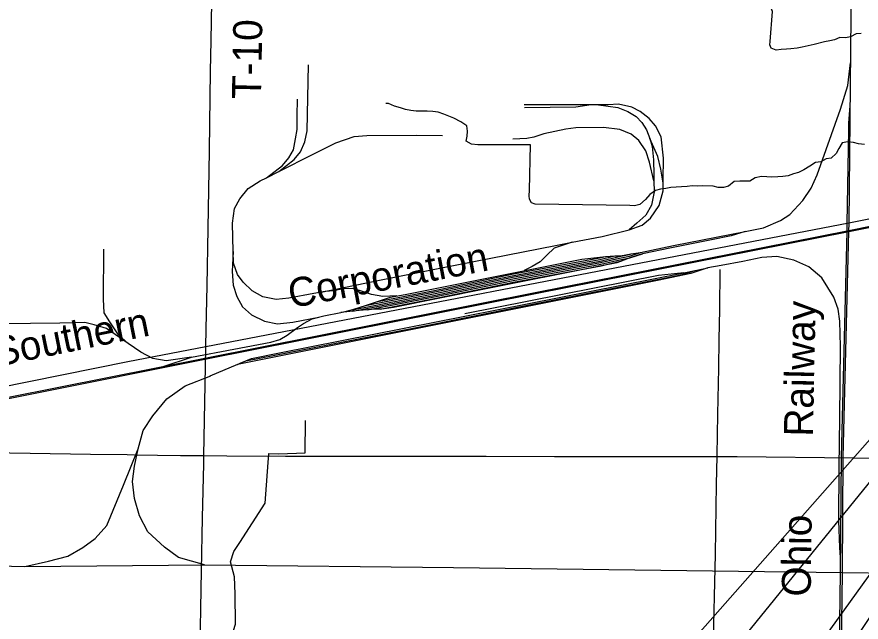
# Model space of a CAD drawing. Extents: x -21.7 to 34, y 0 to 22.
# Drawn here: x 24.265 to 25.914, y 16.163 to 17.347 of the extents above; entities that cross this region are included whole.
import ezdxf

# ---------------------------------------------------------------- set-up
doc = ezdxf.new("R2010")
doc.units = 0
for name, color, linetype in [('GM_X_County_Road', 7, 'Continuous'), ('GM_X_Minor_River', 7, 'Continuous'), ('GM_X_Rail_Line', 7, 'Continuous'), ('GM_X_Rail_Line_Text', 7, 'Continuous'), ('GM_X_Township_Road', 7, 'Continuous'), ('GM_X_Township_Road_Text', 7, 'Continuous'), ('SH_Text', 7, 'Continuous')]:
    doc.layers.add(name, color=color, linetype=linetype)

msp = doc.modelspace()

# ---------------------------------------------------------------- linework, layer by layer
at = {"layer": 'GM_X_County_Road'}
for points in [[(23.6256, 16.4644), (23.6379, 16.4668), (23.6898, 16.4767), (23.7751, 16.4941), (23.7934, 16.4974), (23.8057, 16.499), (23.818, 16.5001), (23.8304, 16.5007), (23.8521, 16.5009), (23.9236, 16.4998), (23.9951, 16.4988), (24.0915, 16.4969), (24.2904, 16.4939), (24.4085, 16.4918), (24.4798, 16.491), (24.4945, 16.4906), (24.5845, 16.4894), (24.6301, 16.4891)], [(24.6301, 16.4891), (24.6746, 16.4888), (24.7897, 16.488), (24.8643, 16.4882), (24.8953, 16.4881), (24.9451, 16.488), (25.0104, 16.488), (25.0725, 16.4878), (25.1223, 16.4878), (25.1813, 16.4879), (25.3149, 16.4876), (25.346, 16.4875), (25.4734, 16.4872), (25.5014, 16.4871), (25.6319, 16.4875), (25.6331, 16.4875)], [(25.6331, 16.4875), (25.6723, 16.4872), (25.8993, 16.4845), (25.966, 16.4842)]]:
    msp.add_lwpolyline(points, dxfattribs=at)
at = {"layer": 'GM_X_Minor_River'}
for points in [[(25.7364, 17.2987), (25.7411, 17.3574), (25.7379, 17.3662), (25.7315, 17.369), (25.712, 17.3748), (25.6478, 17.391), (25.6434, 17.3975), (25.6414, 17.4075), (25.636, 17.4194), (25.6031, 17.4402), (25.5644, 17.4395)], [(25.9147, 17.3144), (25.9048, 17.3139), (25.8933, 17.3081), (25.8837, 17.306), (25.8727, 17.3063), (25.8624, 17.3019), (25.8529, 17.3003), (25.8429, 17.2978), (25.8223, 17.293), (25.8109, 17.2906), (25.7991, 17.2874), (25.7892, 17.2854), (25.777, 17.2843), (25.7683, 17.2835), (25.758, 17.283), (25.7485, 17.2821), (25.7383, 17.2854), (25.7362, 17.2924), (25.7364, 17.2987)], [(25.1652, 17.097), (25.1527, 17.098), (25.1426, 17.1036), (25.1444, 17.1134), (25.1453, 17.1236), (25.1437, 17.1339), (25.1321, 17.1418), (25.1182, 17.1489), (25.0987, 17.1569), (25.0878, 17.1606), (25.0772, 17.1616), (25.0662, 17.1626), (25.0548, 17.1625), (25.045, 17.1627), (25.0344, 17.1637), (25.0238, 17.1658), (25.014, 17.1691), (25.0023, 17.1724), (24.9907, 17.1776), (24.9857, 17.1777)], [(25.4625, 16.978), (25.2771, 16.9806), (25.2699, 16.9835), (25.2663, 16.9907), (25.2657, 16.9972), (25.2663, 17.0078), (25.2684, 17.0966), (25.1652, 17.097)], [(25.921, 17.0972), (25.9093, 17.0986), (25.8995, 17.1015), (25.8881, 17.1029), (25.877, 17.1004), (25.8707, 17.0896), (25.8656, 17.0795), (25.8559, 17.0709), (25.8463, 17.0693), (25.8356, 17.0638), (25.8253, 17.0621), (25.8138, 17.0548), (25.8022, 17.0478), (25.7919, 17.0428), (25.7823, 17.0403), (25.7716, 17.036), (25.7613, 17.0351), (25.7514, 17.0342), (25.74, 17.0337), (25.7302, 17.0339), (25.7196, 17.0345), (25.7074, 17.0325), (25.697, 17.0259), (25.6867, 17.0254), (25.6773, 17.0256), (25.6662, 17.0247), (25.6554, 17.0158), (25.6455, 17.013), (25.6352, 17.0136), (25.6254, 17.0161), (25.605, 17.0166), (25.5951, 17.0157), (25.5841, 17.0163), (25.5746, 17.015), (25.5636, 17.0148), (25.5423, 17.013), (25.5324, 17.0114), (25.5225, 17.0101), (25.5126, 17.0073), (25.5017, 16.9995), (25.4932, 16.9899), (25.4822, 16.9799), (25.4712, 16.9777), (25.4625, 16.978)], [(24.7767, 16.4927), (24.8276, 16.4946), (24.8286, 16.5576)], [(24.1157, 15.4505), (24.1225, 15.4647), (24.1423, 15.4696), (24.1622, 15.4741), (24.1812, 15.4756), (24.1982, 15.4752), (24.4418, 15.4747), (24.4643, 15.495), (24.5971, 15.4958), (24.6104, 16.0334), (24.6316, 16.047), (24.6541, 16.0677), (24.6743, 16.1033), (24.6915, 16.1595), (24.6914, 16.2191), (24.6895, 16.2518), (24.6818, 16.2815), (24.6888, 16.3019), (24.7005, 16.3195), (24.7498, 16.3958), (24.757, 16.4932), (24.7767, 16.4927)]]:
    msp.add_lwpolyline(points, dxfattribs=at)
at = {"layer": 'GM_X_Rail_Line'}
for p, q in [((25.401, 17.175), (25.3871, 17.175)), ((24.7523, 17.0321), (24.7765, 17.0445)), ((25.4147, 16.8783), (25.433, 16.8794)), ((25.4647, 16.8833), (25.4834, 16.8862)), ((25.568, 16.8466), (25.5897, 16.8509)), ((25.5897, 16.8509), (25.6147, 16.8559)), ((24.9212, 16.7713), (24.8978, 16.7692)), ((24.6957, 16.6673), (24.6413, 16.6441)), ((24.2799, 16.272), (24.6309, 16.2756))]:
    msp.add_line(p, q, dxfattribs=at)
for points in [[(25.8368, 14.1), (25.8424, 14.4841), (25.8672, 15.4825), (25.8776, 16.2603), (25.8795, 16.4862), (25.8906, 16.927), (25.8907, 16.9438), (25.8961, 17.4845), (25.9239, 18.7551), (25.935, 19.5978), (25.9554, 20.5461), (25.9616, 20.9)], [(23.5167, 16.459), (23.6295, 16.4808), (23.9621, 16.5465), (24.6321, 16.6797), (25.2774, 16.8081), (25.8901, 16.9293), (26.3845, 17.0293), (27.0776, 17.1675), (27.7467, 17.2984), (28.3715, 17.4275), (28.9889, 17.5495), (29.6221, 17.6814), (30.2791, 17.8098), (30.3167, 17.8172)], [(25.8905, 16.9443), (26.7077, 17.1083), (26.7688, 17.1586), (26.8119, 17.2101), (26.8634, 17.276), (26.8946, 17.3324), (26.9509, 17.3923), (27.006, 17.4474), (27.0347, 17.4689), (27.0802, 17.4809), (27.5534, 17.4838), (27.9584, 17.4827), (28.1647, 17.4796), (28.575, 17.4796), (29.0617, 17.5773), (30.0904, 17.7802), (30.3167, 17.8248)], [(23.5167, 16.4567), (23.6289, 16.4784), (23.9619, 16.5433), (24.6317, 16.6775), (25.2779, 16.8058), (25.8906, 16.927), (26.3849, 17.0271), (27.078, 17.1653), (27.7471, 17.2961), (28.3719, 17.4252), (28.9894, 17.5472), (29.6225, 17.6791), (30.2796, 17.8076), (30.3167, 17.8149)], [(25.6876, 16.927), (25.7233, 16.9345), (25.757, 16.9485), (25.7751, 16.9608), (25.8006, 16.988), (25.817, 17.0118), (25.8285, 17.0381), (25.8737, 17.1664), (25.8884, 17.2129), (25.8938, 17.2569)], [(24.7765, 17.0445), (24.8063, 17.0679), (24.8191, 17.0831), (24.8273, 17.1024), (24.8318, 17.1242), (24.8343, 17.2532)], [(24.7523, 17.0321), (24.7833, 17.056), (24.7961, 17.0716), (24.8051, 17.0872), (24.8092, 17.1082), (24.8121, 17.1267), (24.8121, 17.1534), (24.8129, 17.1863)], [(25.3871, 17.175), (25.3513, 17.1747), (25.2556, 17.1747)], [(25.3871, 17.175), (25.3571, 17.1702), (25.2564, 17.169)], [(25.5275, 17.0218), (25.5277, 17.0276), (25.5281, 17.0708), (25.5235, 17.1123), (25.5124, 17.1336), (25.5001, 17.1484), (25.4824, 17.1616), (25.4664, 17.1706), (25.4401, 17.176), (25.42, 17.1752), (25.401, 17.175)], [(25.401, 17.175), (25.4389, 17.1698), (25.4586, 17.162), (25.475, 17.1521), (25.4857, 17.1406), (25.4952, 17.1262), (25.5013, 17.109)], [(25.8526, 14.8964), (25.8499, 14.9355), (25.8634, 15.4826), (25.8739, 16.2603), (25.8757, 16.4863), (25.8868, 16.9271), (25.887, 16.9438), (25.8904, 17.1251), (25.8905, 17.1392), (25.893, 17.1728)], [(25.5093, 17.0264), (25.5009, 17.0625), (25.4939, 17.0851), (25.48, 17.1053), (25.4648, 17.1176), (25.4426, 17.1267), (25.4109, 17.1304), (25.3571, 17.1299), (25.3374, 17.1275), (25.3156, 17.123), (25.2942, 17.1184), (25.2749, 17.1119), (25.2609, 17.1094), (25.2338, 17.1077)], [(24.7765, 17.0445), (24.8433, 17.0786), (24.8877, 17.1008), (24.9235, 17.1127), (24.9481, 17.1151), (25.0459, 17.1156), (25.0961, 17.1147)], [(25.5275, 17.0218), (25.5227, 17.0494), (25.517, 17.074), (25.5013, 17.109)], [(25.5013, 17.109), (25.5059, 17.0934), (25.5087, 17.0671), (25.5092, 17.0379), (25.5093, 17.0264)], [(24.6871, 16.8883), (24.6859, 16.9433), (24.69, 16.9725), (24.7003, 16.9914), (24.7163, 17.0112), (24.7402, 17.026), (24.7523, 17.0321)], [(25.5093, 17.0264), (25.5096, 17.0046), (25.5046, 16.9787), (25.4935, 16.9594), (25.4763, 16.9438), (25.4611, 16.9306)], [(25.4611, 16.9306), (25.4866, 16.9396), (25.503, 16.9536), (25.5194, 16.9783), (25.5272, 17.007), (25.5275, 17.0218)], [(23.5167, 16.4779), (24.4815, 16.6733), (25.8905, 16.9443)], [(25.3497, 16.9061), (25.408, 16.9174), (25.4611, 16.9306)], [(25.4834, 16.8862), (25.5475, 16.9), (25.6876, 16.927), (25.6603, 16.9185), (25.6221, 16.9109), (25.5406, 16.8948), (25.4903, 16.8843), (25.4871, 16.8833)], [(24.8561, 16.808), (24.9732, 16.8324), (25.094, 16.8562), (25.3172, 16.8998), (25.3497, 16.9061)], [(25.3497, 16.9061), (25.3143, 16.8944), (25.3, 16.8809), (25.2872, 16.8677), (25.2716, 16.8591), (25.2558, 16.8507)], [(24.4823, 16.708), (24.4634, 16.7252), (24.4461, 16.7507), (24.4354, 16.768), (24.4338, 16.7951), (24.4346, 16.8929)], [(24.6871, 16.8883), (24.6851, 16.8488), (24.6871, 16.8221), (24.6945, 16.7999), (24.7056, 16.7802), (24.7229, 16.7646), (24.7484, 16.7518), (24.7739, 16.7465), (24.8039, 16.7498), (24.8547, 16.76)], [(24.8561, 16.808), (24.8446, 16.8061), (24.7961, 16.797), (24.771, 16.7946), (24.7455, 16.7995), (24.7241, 16.811), (24.7069, 16.8283), (24.6958, 16.8435), (24.688, 16.8653), (24.6871, 16.8883)], [(24.9206, 16.7744), (25.0819, 16.8061), (25.2332, 16.8377), (25.4045, 16.8695), (25.4413, 16.8781), (25.4609, 16.882), (25.4647, 16.8833)], [(24.9212, 16.7713), (25.0826, 16.803), (25.2338, 16.8346), (25.4051, 16.8665), (25.4419, 16.8751), (25.4617, 16.879), (25.4834, 16.8862)], [(24.9461, 16.7826), (25.0813, 16.8091), (25.2326, 16.8407), (25.4038, 16.8726), (25.433, 16.8794)], [(24.95, 16.7738), (25.0832, 16.8), (25.2344, 16.8316), (25.4058, 16.8635), (25.4426, 16.872), (25.4625, 16.876), (25.4871, 16.8833)], [(24.969, 16.7902), (24.9944, 16.7991), (25.0263, 16.8047), (25.3686, 16.8734), (25.4097, 16.878), (25.4147, 16.8783)], [(24.969, 16.7902), (25.0807, 16.8122), (25.232, 16.8438), (25.4032, 16.8756), (25.4147, 16.8783)], [(25.433, 16.8794), (25.4439, 16.88), (25.4647, 16.8833)], [(25.4871, 16.8833), (25.4646, 16.8764), (25.4457, 16.8695)], [(25.8741, 16.29), (25.8725, 16.3092), (25.8708, 16.3614), (25.8713, 16.4666), (25.8725, 16.5623), (25.8741, 16.7025), (25.8729, 16.7518), (25.8696, 16.7752), (25.861, 16.7991), (25.8376, 16.8369), (25.8121, 16.8583), (25.7825, 16.871), (25.7496, 16.8784), (25.72, 16.8763), (25.683, 16.8685), (25.6411, 16.8611), (25.6147, 16.8559)], [(24.9744, 16.7754), (25.0838, 16.797), (25.235, 16.8285), (25.4064, 16.8604), (25.4433, 16.869), (25.4457, 16.8695)], [(25.4457, 16.8695), (25.4367, 16.8662), (25.4035, 16.8596), (25.1782, 16.8146), (25.0004, 16.7784), (24.9823, 16.7758), (24.9744, 16.7754)], [(25.6147, 16.8559), (25.5816, 16.8449), (25.5198, 16.8324), (24.6957, 16.6673)], [(24.7118, 16.6742), (25.0388, 16.7381), (25.2593, 16.7828), (25.5454, 16.8393), (25.5649, 16.8434), (25.5897, 16.8509)], [(24.7118, 16.6742), (24.7232, 16.679), (24.778, 16.6897), (25.568, 16.8466)], [(25.568, 16.8466), (25.5182, 16.8414), (25.1397, 16.7666)], [(25.0068, 16.8013), (24.9794, 16.8003), (24.9572, 16.804), (24.9362, 16.8114), (24.9202, 16.8155), (24.9009, 16.8151), (24.8848, 16.8114), (24.8667, 16.8098), (24.8561, 16.808)], [(24.5501, 16.6634), (24.6061, 16.6814), (24.6883, 16.6972), (24.7606, 16.7106), (24.7787, 16.7162), (24.7929, 16.7245), (24.8129, 16.7393), (24.8248, 16.7471), (24.8415, 16.7564), (24.8642, 16.7626), (24.8974, 16.7692), (24.9231, 16.7751), (24.9461, 16.7826)], [(24.9461, 16.7826), (24.9596, 16.7869), (24.969, 16.7902)], [(24.95, 16.7738), (24.9336, 16.7725), (24.9212, 16.7713)], [(24.9744, 16.7754), (24.9652, 16.7751), (24.95, 16.7738)], [(24.4823, 16.708), (24.4395, 16.7376), (24.4157, 16.745), (24.3976, 16.7491), (24.3483, 16.7482), (24.234, 16.7466)], [(24.6061, 16.6814), (24.5565, 16.6744), (24.5299, 16.6792), (24.5069, 16.6915), (24.4823, 16.708)], [(24.6957, 16.6673), (24.7007, 16.6695), (24.7118, 16.6742)], [(24.5015, 16.502), (24.5111, 16.538), (24.5302, 16.5667), (24.5578, 16.6003), (24.5937, 16.6255), (24.6433, 16.6448)], [(24.2799, 16.272), (24.3266, 16.2828), (24.3638, 16.2924), (24.3937, 16.3091), (24.4177, 16.3271), (24.4404, 16.3523), (24.4728, 16.4314), (24.5015, 16.502)], [(24.6309, 16.2756), (24.5806, 16.29), (24.553, 16.3103), (24.5207, 16.3403), (24.5039, 16.3714), (24.4943, 16.405), (24.4907, 16.4385), (24.4943, 16.4685), (24.5015, 16.502)], [(23.5167, 16.2873), (23.9204, 16.2834), (24.0979, 16.2768), (24.2799, 16.272)], [(24.6309, 16.2756), (25.1178, 16.2705), (25.8774, 16.2608)], [(25.8774, 16.2608), (26.0821, 16.258), (27.0998, 16.252), (27.5176, 16.2418), (28.8453, 16.222), (29.9847, 16.211), (30.3167, 16.2074)]]:
    msp.add_lwpolyline(points, dxfattribs=at)
at = {"layer": 'GM_X_Township_Road'}
for points in [[(24.6301, 16.4891), (24.6325, 16.6283), (24.6344, 16.7371), (24.6361, 16.8211), (24.6381, 16.933), (24.6407, 17.0853), (24.6415, 17.1381), (24.6432, 17.2407), (24.6442, 17.2998), (24.6459, 17.4148), (24.6467, 17.4677), (24.6473, 17.4912)], [(25.6331, 16.4875), (25.6332, 16.489), (25.6339, 16.5294), (25.6346, 16.5698), (25.6362, 16.66), (25.6371, 16.716), (25.638, 16.775), (25.639, 16.8527)], [(23.6256, 16.4644), (23.6379, 16.4668), (23.6898, 16.4767), (23.7751, 16.4941), (23.7934, 16.4974), (23.8057, 16.499), (23.818, 16.5001), (23.8304, 16.5007), (23.8521, 16.5009), (23.9236, 16.4998), (23.9951, 16.4988), (24.0915, 16.4969), (24.2904, 16.4939), (24.4085, 16.4918), (24.4798, 16.491), (24.4945, 16.4906), (24.5845, 16.4894), (24.6301, 16.4891)], [(24.6092, 15.4887), (24.6104, 15.5436), (24.612, 15.615), (24.6132, 15.6834), (24.6165, 15.8264), (24.6191, 15.9476), (24.6196, 15.9881), (24.6206, 16.0316), (24.6224, 16.1155), (24.6247, 16.2274), (24.6255, 16.2647), (24.6276, 16.3672), (24.6298, 16.4729), (24.6301, 16.4891)], [(24.6301, 16.4891), (24.6746, 16.4888), (24.7897, 16.488), (24.8643, 16.4882), (24.8953, 16.4881), (24.9451, 16.488), (25.0104, 16.488), (25.0725, 16.4878), (25.1223, 16.4878), (25.1813, 16.4879), (25.3149, 16.4876), (25.346, 16.4875), (25.4734, 16.4872), (25.5014, 16.4871), (25.6319, 16.4875), (25.6331, 16.4875)], [(25.6234, 15.9906), (25.6244, 16.0508), (25.6255, 16.1037), (25.6295, 16.2964), (25.632, 16.4331), (25.6331, 16.4875)], [(25.6331, 16.4875), (25.6723, 16.4872), (25.8993, 16.4845), (25.966, 16.4842)]]:
    msp.add_lwpolyline(points, dxfattribs=at)
at = {"layer": 'SH_Text'}
for points in [[(23.5845, 13.5445), (26.7756, 17.4787), (23.5845, 13.8593)], [(23.5845, 12.6836), (26.8092, 17.4787), (23.5845, 12.9954)]]:
    msp.add_lwpolyline(points, close=True, dxfattribs=at)

# ---------------------------------------------------------------- texts
at = {"layer": 'GM_X_Rail_Line_Text'}
for s, height, rotation, p in [('Corporation', 0.056629, 10.849, (24.8005, 16.7772)), ('Railway', 0.05663, 88.7615, (25.8199, 16.5258)), ('Southern', 0.05663, 11.5058, (24.2257, 16.6628)), ('Ohio', 0.05663, 89.2367, (25.8157, 16.2132))]:
    msp.add_text(s, height=height, rotation=rotation, dxfattribs=at).set_placement(p)
at = {"layer": 'GM_X_Township_Road_Text'}
msp.add_text('T-10', height=0.05682, rotation=88.9454, dxfattribs=at).set_placement((24.7415, 17.1855))

doc.saveas('drawing.dxf')
